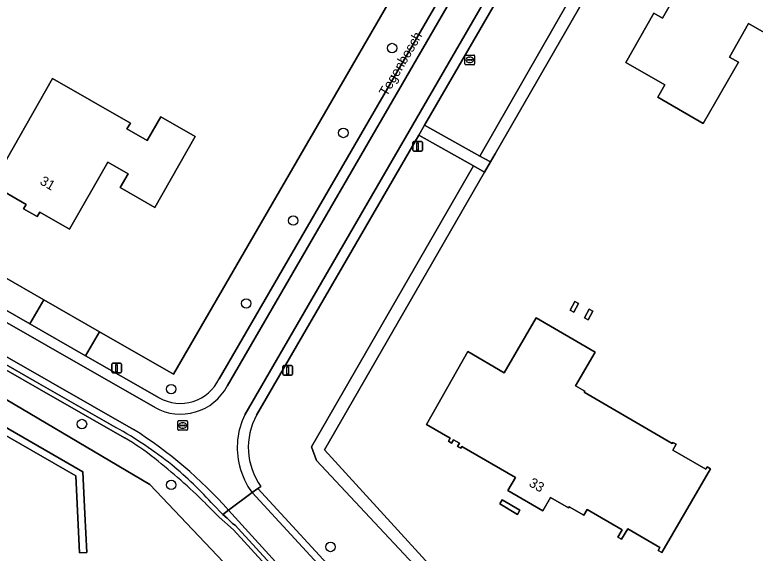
# Model space of a CAD drawing. Extents: x 156502 to 159075, y 384229 to 386100.
# Drawn here: x 157141.1 to 157217.5, y 385707.8 to 385763.4 of the extents above; entities that cross this region are included whole.
import ezdxf

# ---------------------------------------------------------------- set-up
doc = ezdxf.new("R2010")
doc.units = 0
for name, color, linetype in [('IMGEO_Berm_groen', 7, 'Continuous'), ('IMGEO_Berm_open', 7, 'Continuous'), ('IMGEO_Boom', 7, 'Continuous'), ('IMGEO_Erf', 7, 'Continuous'), ('IMGEO_Groenvoorziening', 7, 'Continuous'), ('IMGEO_Hek', 7, 'Continuous'), ('IMGEO_Kolk', 7, 'Continuous'), ('IMGEO_Lichtmast', 7, 'Continuous'), ('IMGEO_Muur', 7, 'Continuous'), ('IMGEO_Openbare_ruimte_label', 7, 'Continuous'), ('IMGEO_Pand', 7, 'Continuous'), ('IMGEO_Pand_nummerreeks', 7, 'Continuous'), ('IMGEO_Rijbaan_lokaal_gesloten', 7, 'Continuous'), ('IMGEO_Rijbaan_lokaal_halfverhard', 7, 'Continuous'), ('IMGEO_Rijbaan_lokaal_open', 7, 'Continuous'), ('IMGEO_Rioolput', 7, 'Continuous'), ('IMGEO_Voetpad_open', 7, 'Continuous')]:
    doc.layers.add(name, color=color, linetype=linetype)

msp = doc.modelspace()

# ---------------------------------------------------------------- linework, layer by layer
at = {"layer": 'IMGEO_Berm_groen'}
for points in [[(157205.798, 385801.093), (157204.517, 385807.457), (157201.732, 385802.693), (157157.489, 385726.3), (157149.855, 385730.69), (157148.433, 385728.196), (157156.009, 385723.887)], [(157162.191, 385725.838), (157205.798, 385801.093)]]:
    msp.add_lwpolyline(points, dxfattribs=at)
msp.add_lwpolyline([(157131.197, 385741.421), (157130.921, 385741.579), (157129.529, 385739.04), (157142.675, 385731.515), (157144.11, 385733.995)], close=True, dxfattribs=at)
msp.add_arc((157158.202, 385727.709), 4.406, 240.15556, 334.87517, dxfattribs=at)
at = {"layer": 'IMGEO_Berm_open'}
for points in [[(157122.692, 385736.917), (157122.629, 385736.809), (157134.443, 385730.048), (157136.699, 385728.757), (157143.67, 385724.768), (157152.438, 385719.741)], [(157151.556, 385720.809), (157143.135, 385725.639), (157131.139, 385732.504), (157122.862, 385737.211), (157122.692, 385736.917)], [(157160.802, 385712.985), (157162.212, 385711.565), (157163.676, 385710.253), (157166.599, 385707.057), (157167.262, 385706.33), (157167.069, 385705.548), (157165.011, 385703.658), (157164.518, 385703.205), (157164.798, 385702.861), (157164.874, 385702.768), (157167.579, 385705.215), (157167.865, 385706.331), (157164.162, 385710.397), (157163.893, 385710.681), (157163.596, 385710.912), (157163.015, 385711.443), (157162.571, 385711.837), (157162.514, 385711.888), (157161.64, 385712.801)]]:
    msp.add_lwpolyline(points, dxfattribs=at)
for centre, radius, start, end in [((157132.493, 385686.215), 39.499, 51.08239, 61.14287), ((157139.852, 385698.063), 25.067, 51.20506, 59.86057), ((157114.204, 385665.314), 66.663, 45.65222, 51.65962), ((157131.825, 385685.972), 40.109, 41.98216, 50.5579)]:
    msp.add_arc(centre, radius, start, end, dxfattribs=at)
at = {"layer": 'IMGEO_Boom'}
for centre in [(157180.048, 385759.963), (157175.016, 385751.204), (157169.847, 385742.161), (157164.994, 385733.609), (157157.253, 385724.77), (157148.052, 385721.166), (157157.263, 385714.892), (157173.691, 385708.485)]:
    msp.add_circle(centre, 0.489, dxfattribs=at)
at = {"layer": 'IMGEO_Erf'}
for points in [[(157131.197, 385741.421), (157144.11, 385733.995), (157149.855, 385730.69), (157157.489, 385726.3), (157201.732, 385802.693), (157194.383, 385806.952), (157190.645, 385800.522), (157181.547, 385805.765), (157180.811, 385804.505), (157181.113, 385804.328), (157176.827, 385796.988), (157169.771, 385801.108), (157174.018, 385808.44), (157178.814, 385805.661), (157179.553, 385806.928), (157179.259, 385807.099), (157183.031, 385813.57), (157159.85, 385827.054)], [(157300.611, 385725.628), (157250.886, 385753.432), (157232.436, 385728.117), (157222.966, 385734.271), (157242.958, 385769.961), (157246.925, 385776.791), (157216.71, 385794.202), (157213.481, 385788.661), (157210.483, 385783.472), (157204.894, 385773.824), (157204.086, 385772.373), (157190.66, 385749.032), (157190.191, 385748.219), (157189.585, 385747.166), (157173.064, 385718.503), (157188.558, 385701.554)], [(157130.083, 385674.016), (157162.143, 385703.286), (157165.17, 385704.25), (157155.054, 385714.92), (157136.059, 385726.15)], [(157134.817, 385723.916), (157148.149, 385716.222), (157148.362, 385711.898), (157148.558, 385707.925), (157147.812, 385707.892), (157147.432, 385715.812), (157133.773, 385723.654)]]:
    msp.add_lwpolyline(points, dxfattribs=at)
for points in [[(157216.825, 385762.498), (157214.836, 385759.028), (157215.782, 385758.513), (157212.125, 385752.188), (157207.442, 385754.89), (157208.164, 385756.155), (157204.143, 385758.489), (157207.06, 385763.557), (157207.934, 385763.062), (157209.905, 385766.51), (157209.04, 385767.011), (157210.228, 385769.058), (157211.364, 385771.036), (157210.092, 385771.773), (157212.805, 385776.435), (157227.391, 385767.994), (157224.692, 385763.333), (157223.414, 385764.038), (157221.09, 385760.054)], [(157145.011, 385756.807), (157153.044, 385752.202), (157152.682, 385751.64), (157154.769, 385750.435), (157156.174, 385752.869), (157159.745, 385750.827), (157155.568, 385743.525), (157151.995, 385745.568), (157152.803, 385746.981), (157150.715, 385748.193), (157146.759, 385741.271), (157143.69, 385743.027), (157143.418, 385742.572), (157142.025, 385743.36), (157142.291, 385743.83), (157136.743, 385747.004), (157136.902, 385747.281), (157138.903, 385746.106)], [(157198.789, 385732.728), (157198.416, 385732.933), (157198.908, 385733.827), (157199.28, 385733.622)], [(157200.256, 385731.922), (157199.883, 385732.127), (157200.374, 385733.02), (157200.747, 385732.816)], [(157212.394, 385716.506), (157212.545, 385716.767), (157212.9, 385716.561), (157207.88, 385707.905), (157207.492, 385708.134), (157207.663, 385708.425), (157204.36, 385710.352), (157203.719, 385709.283), (157203.343, 385709.503), (157203.783, 385710.251), (157200.181, 385712.353), (157199.832, 385711.755), (157198.312, 385712.63), (157198.242, 385712.509), (157196.392, 385713.576), (157195.606, 385712.212), (157191.984, 385714.299), (157192.772, 385715.665), (157187.236, 385718.855), (157187.126, 385718.663), (157186.796, 385718.851), (157186.992, 385719.194), (157186.385, 385719.542), (157186.189, 385719.199), (157185.859, 385719.388), (157186.052, 385719.726), (157183.587, 385721.136), (157187.86, 385728.639), (157191.62, 385726.449), (157194.896, 385732.112), (157200.992, 385728.586), (157198.967, 385725.104), (157199.927, 385724.546), (157199.867, 385724.443), (157208.946, 385719.168), (157209.006, 385719.272), (157209.343, 385719.076), (157208.997, 385718.479)], [(157192.972, 385711.834), (157191.144, 385712.919), (157191.405, 385713.359), (157193.232, 385712.273)]]:
    msp.add_lwpolyline(points, close=True, dxfattribs=at)
at = {"layer": 'IMGEO_Groenvoorziening'}
for points in [[(157202.954, 385773.026), (157197.423, 385776.216), (157183.392, 385751.998), (157189.099, 385748.819)], [(157204.086, 385772.373), (157203.479, 385772.723), (157202.954, 385773.026), (157189.099, 385748.819), (157189.61, 385748.533), (157190.191, 385748.219), (157190.66, 385749.032)], [(157173.064, 385718.503), (157189.585, 385747.166), (157188.458, 385747.796), (157171.716, 385718.804), (157172.234, 385717.388), (157187.763, 385700.816), (157188.558, 385701.554)]]:
    msp.add_lwpolyline(points, close=True, dxfattribs=at)
for points in [[(157188.458, 385747.796), (157182.79, 385750.96), (157166.062, 385722.087)], [(157166.5, 385714.736), (157166.189, 385714.515), (157177.304, 385702.459), (157182.888, 385696.288), (157187.763, 385700.816), (157172.234, 385717.388), (157171.716, 385718.804), (157188.458, 385747.796)], [(157152.438, 385719.741), (157143.67, 385724.768), (157136.699, 385728.757), (157135.417, 385726.51), (157136.059, 385726.15), (157155.054, 385714.92), (157165.17, 385704.25), (157165.011, 385703.658), (157167.069, 385705.548), (157167.262, 385706.33), (157166.599, 385707.057), (157163.676, 385710.253), (157162.212, 385711.565), (157160.802, 385712.985)]]:
    msp.add_lwpolyline(points, dxfattribs=at)
for centre, radius, start, end in [((157172.15, 385718.761), 6.937, 151.35104, 215.46869), ((157139.852, 385698.063), 25.067, 51.20506, 59.86057), ((157114.204, 385665.314), 66.663, 45.65222, 51.65962)]:
    msp.add_arc(centre, radius, start, end, dxfattribs=at)
at = {"layer": 'IMGEO_Hek'}
for points in [[(157149.855, 385730.69), (157157.489, 385726.3), (157201.732, 385802.693)], [(157131.197, 385741.421), (157144.11, 385733.995)], [(157144.11, 385733.995), (157149.855, 385730.69)]]:
    msp.add_lwpolyline(points, dxfattribs=at)
at = {"layer": 'IMGEO_Kolk'}
for p, q in [((157187.556, 385758.32), (157187.556, 385759.172)), ((157187.631, 385759.246), (157188.483, 385759.246)), ((157188.044, 385759.026), (157188.069, 385759.026)), ((157188.557, 385759.172), (157188.557, 385758.32)), ((157187.815, 385758.74), (157187.815, 385758.752)), ((157188.253, 385758.703), (157187.855, 385758.703)), ((157187.858, 385758.789), (157188.256, 385758.789)), ((157188.067, 385758.466), (157188.042, 385758.466)), ((157188.299, 385758.752), (157188.299, 385758.74)), ((157188.483, 385758.246), (157187.631, 385758.246))]:
    msp.add_line(p, q, dxfattribs=at)
for points in [[(157187.556, 385758.32), (157187.556, 385759.172)], [(157187.631, 385759.246), (157188.483, 385759.246)], [(157188.557, 385759.172), (157188.557, 385758.32)], [(157188.483, 385758.246), (157187.631, 385758.246)]]:
    msp.add_lwpolyline(points, dxfattribs=at)
for centre, radius, start, end in [((157187.633, 385759.17), 0.0765, 91.55205, 178.44795), ((157187.633, 385759.17), 0.0765, 91.55205, 178.44795), ((157188.481, 385759.17), 0.0765, 1.55205, 88.44795), ((157188.481, 385759.17), 0.0765, 1.55205, 88.44795), ((157187.633, 385758.322), 0.0765, 181.55205, 268.44795), ((157187.633, 385758.322), 0.0765, 181.55205, 268.44795), ((157187.855, 385758.749), 0.0403, 85.87752, 175.75265), ((157187.852, 385758.739), 0.0366, 178.93798, 274.71019), ((157188.256, 385758.746), 0.043, 264.86636, 352.45326), ((157188.26, 385758.751), 0.0386, 1.73085, 96.63898), ((157188.481, 385758.322), 0.0765, 271.55205, 358.44795), ((157188.481, 385758.322), 0.0765, 271.55205, 358.44795)]:
    msp.add_arc(centre, radius, start, end, dxfattribs=at)
for centre, major_axis, ratio, start_param, end_param in [((157188.043, 385758.746), (-0.387, 0.002), 0.722429, 4.712389, 7.853982), ((157188.068, 385758.746), (-0.39, 0.002), 0.717154, 1.570796, 4.712389)]:
    msp.add_ellipse(centre, major_axis=major_axis, ratio=ratio, start_param=start_param, end_param=end_param, dxfattribs=at)
at = {"layer": 'IMGEO_Lichtmast'}
for p, q in [((157182.18, 385749.418), (157182.18, 385750.218)), ((157182.18, 385750.218), (157182.18, 385749.418)), ((157182.28, 385750.318), (157183.07, 385750.318)), ((157183.07, 385750.318), (157182.28, 385750.318)), ((157183.17, 385750.218), (157183.17, 385749.418)), ((157183.17, 385749.418), (157183.17, 385750.218)), ((157183.07, 385749.318), (157182.28, 385749.318)), ((157182.28, 385749.318), (157183.07, 385749.318)), ((157151.129, 385726.54), (157151.129, 385727.34)), ((157151.129, 385727.34), (157151.129, 385726.54)), ((157151.229, 385727.44), (157152.019, 385727.44)), ((157152.019, 385727.44), (157151.229, 385727.44)), ((157152.119, 385727.34), (157152.119, 385726.54)), ((157152.119, 385726.54), (157152.119, 385727.34)), ((157168.777, 385726.301), (157168.777, 385727.101)), ((157168.777, 385727.101), (157168.777, 385726.301)), ((157168.877, 385727.201), (157169.667, 385727.201)), ((157169.667, 385727.201), (157168.877, 385727.201)), ((157169.767, 385727.101), (157169.767, 385726.301)), ((157169.767, 385726.301), (157169.767, 385727.101)), ((157152.019, 385726.44), (157151.229, 385726.44)), ((157151.229, 385726.44), (157152.019, 385726.44)), ((157169.667, 385726.201), (157168.877, 385726.201)), ((157168.877, 385726.201), (157169.667, 385726.201))]:
    msp.add_line(p, q, dxfattribs=at)
for points in [[(157182.6, 385750.193), (157182.75, 385750.193), (157182.75, 385749.443), (157182.6, 385749.443), (157182.6, 385750.193)], [(157151.549, 385727.315), (157151.699, 385727.315), (157151.699, 385726.565), (157151.549, 385726.565), (157151.549, 385727.315)], [(157169.197, 385727.076), (157169.347, 385727.076), (157169.347, 385726.326), (157169.197, 385726.326), (157169.197, 385727.076)]]:
    msp.add_lwpolyline(points, dxfattribs=at)
for centre, start, end in [((157182.28, 385750.218), 90, 180), ((157182.28, 385750.218), 90, 180), ((157183.07, 385750.218), 0, 90), ((157183.07, 385750.218), 360, 90), ((157182.28, 385749.418), 180, 270), ((157182.28, 385749.418), 180, 270), ((157183.07, 385749.418), 270, 0), ((157183.07, 385749.418), 270, 0), ((157151.229, 385727.34), 90, 180), ((157151.229, 385727.34), 90, 180), ((157152.019, 385727.34), 0, 90), ((157152.019, 385727.34), 360, 90), ((157168.877, 385727.101), 90, 180), ((157168.877, 385727.101), 90, 180), ((157169.667, 385727.101), 0, 90), ((157169.667, 385727.101), 360, 90), ((157151.229, 385726.54), 180, 270), ((157151.229, 385726.54), 180, 270), ((157152.019, 385726.54), 270, 0), ((157152.019, 385726.54), 270, 0), ((157168.877, 385726.301), 180, 270), ((157168.877, 385726.301), 180, 270), ((157169.667, 385726.301), 270, 0), ((157169.667, 385726.301), 270, 0)]:
    msp.add_arc(centre, 0.1, start, end, dxfattribs=at)
at = {"layer": 'IMGEO_Muur'}
msp.add_lwpolyline([(157148.362, 385711.898), (157148.149, 385716.222), (157134.817, 385723.916), (157136.059, 385726.15), (157135.417, 385726.51), (157134.821, 385725.475), (157133.773, 385723.654), (157147.432, 385715.812), (157147.812, 385707.892), (157148.558, 385707.925)], close=True, dxfattribs=at)
at = {"layer": 'IMGEO_Pand'}
for points in [[(157227.391, 385767.994), (157212.805, 385776.435), (157210.092, 385771.773), (157211.364, 385771.036), (157210.228, 385769.058), (157209.04, 385767.011), (157209.905, 385766.51), (157207.934, 385763.062), (157207.06, 385763.557), (157204.143, 385758.489), (157208.164, 385756.155), (157207.442, 385754.89), (157212.125, 385752.188), (157215.782, 385758.513), (157214.836, 385759.028), (157216.825, 385762.498), (157221.09, 385760.054), (157223.414, 385764.038), (157224.692, 385763.333)], [(157146.759, 385741.271), (157150.715, 385748.193), (157152.803, 385746.981), (157151.995, 385745.568), (157155.568, 385743.525), (157159.745, 385750.827), (157156.174, 385752.869), (157154.769, 385750.435), (157152.682, 385751.64), (157153.044, 385752.202), (157145.011, 385756.807), (157138.903, 385746.106), (157136.902, 385747.281), (157136.743, 385747.004), (157142.291, 385743.83), (157142.025, 385743.36), (157143.418, 385742.572), (157143.69, 385743.027)], [(157199.28, 385733.622), (157198.908, 385733.827), (157198.416, 385732.933), (157198.789, 385732.728)], [(157200.747, 385732.816), (157200.374, 385733.02), (157199.883, 385732.127), (157200.256, 385731.922)], [(157199.867, 385724.443), (157199.927, 385724.546), (157198.967, 385725.104), (157200.992, 385728.586), (157194.896, 385732.112), (157191.62, 385726.449), (157187.86, 385728.639), (157183.587, 385721.136), (157186.052, 385719.726), (157185.859, 385719.388), (157186.189, 385719.199), (157186.385, 385719.542), (157186.992, 385719.194), (157186.796, 385718.851), (157187.126, 385718.663), (157187.236, 385718.855), (157192.772, 385715.665), (157191.984, 385714.299), (157195.606, 385712.212), (157196.392, 385713.576), (157198.242, 385712.509), (157198.312, 385712.63), (157199.832, 385711.755), (157200.181, 385712.353), (157203.783, 385710.251), (157203.343, 385709.503), (157203.719, 385709.283), (157204.36, 385710.352), (157207.663, 385708.425), (157207.492, 385708.134), (157207.88, 385707.905), (157212.9, 385716.561), (157212.545, 385716.767), (157212.394, 385716.506), (157208.997, 385718.479), (157209.343, 385719.076), (157209.006, 385719.272), (157208.946, 385719.168)], [(157191.144, 385712.919), (157192.972, 385711.834), (157193.232, 385712.273), (157191.405, 385713.359)]]:
    msp.add_lwpolyline(points, close=True, dxfattribs=at)
at = {"layer": 'IMGEO_Rijbaan_lokaal_gesloten'}
for points in [[(157164.84, 385722.131), (157211.808, 385803.246), (157209.184, 385804.754), (157163.025, 385725.068)], [(157155.604, 385722.866), (157042.417, 385787.656)], [(157047.474, 385781.289), (157153.385, 385720.619)], [(157163.176, 385712.295), (157165.598, 385714.094)]]:
    msp.add_lwpolyline(points, dxfattribs=at)
for centre, radius, start, end in [((157158.231, 385727.619), 5.431, 241.07519, 331.97874), ((157171.922, 385718.745), 7.85, 154.44814, 194.01694), ((157126.977, 385679.637), 48.753, 42.05634, 57.20338), ((157171.939, 385718.751), 7.867, 194.03127, 216.29872)]:
    msp.add_arc(centre, radius, start, end, dxfattribs=at)
at = {"layer": 'IMGEO_Rijbaan_lokaal_halfverhard'}
for points in [[(157163.025, 385725.068), (157209.184, 385804.754), (157204.517, 385807.457), (157205.798, 385801.093), (157162.191, 385725.838)], [(157042.417, 385787.656), (157155.604, 385722.866)], [(157156.009, 385723.887), (157148.433, 385728.196), (157142.675, 385731.515), (157129.529, 385739.04), (157126.176, 385740.973), (157123.969, 385742.234), (157121.61, 385743.581), (157120.125, 385744.429), (157117.587, 385745.884), (157112.582, 385748.755), (157110.239, 385750.099), (157105.201, 385752.99), (157098.368, 385756.889), (157083.861, 385765.187), (157082.83, 385765.787), (157073.474, 385771.108), (157068.127, 385774.18), (157061.801, 385777.83), (157055.407, 385781.512), (157048.506, 385785.444), (157044.158, 385787.921)], [(157047.474, 385781.289), (157047.846, 385779.743), (157048.686, 385779.263), (157061.322, 385772.036), (157075.399, 385763.984), (157081.499, 385760.496), (157110.277, 385744.036), (157115.815, 385740.863), (157122.692, 385736.917), (157122.862, 385737.211), (157131.139, 385732.504), (157143.135, 385725.639), (157151.556, 385720.809)], [(157153.385, 385720.619), (157047.474, 385781.289)], [(157161.64, 385712.801), (157162.514, 385711.888), (157162.571, 385711.837), (157163.176, 385712.295)], [(157163.176, 385712.295), (157162.571, 385711.837), (157163.015, 385711.443), (157163.596, 385710.912), (157163.893, 385710.681), (157164.162, 385710.397), (157167.865, 385706.331), (157168.522, 385705.66), (157168.384, 385705.534), (157168.762, 385705.12), (157178.323, 385694.641), (157187.069, 385685.078), (157189.05, 385682.889)], [(157189.594, 385683.36), (157187.603, 385685.561), (157178.854, 385695.127), (157169.409, 385705.442), (157163.176, 385712.295)]]:
    msp.add_lwpolyline(points, dxfattribs=at)
msp.add_lwpolyline([(157166.189, 385714.515), (157165.598, 385714.094), (157176.77, 385701.976), (157182.361, 385695.797), (157182.888, 385696.288), (157177.304, 385702.459)], close=True, dxfattribs=at)
for centre, radius, start, end in [((157158.202, 385727.709), 4.406, 240.15556, 334.87517), ((157158.231, 385727.619), 5.431, 241.07519, 331.97874), ((157132.493, 385686.215), 39.499, 51.08239, 61.14287), ((157126.977, 385679.637), 48.753, 42.05634, 57.20338), ((157131.825, 385685.972), 40.109, 41.98216, 50.5579)]:
    msp.add_arc(centre, radius, start, end, dxfattribs=at)
at = {"layer": 'IMGEO_Rijbaan_lokaal_open'}
for points in [[(157203.866, 385787.336), (157206.888, 385792.553), (157210.12, 385798.131), (157215.153, 385806.818), (157214.196, 385807.371), (157211.808, 385803.246), (157164.84, 385722.131)], [(157166.062, 385722.087), (157182.79, 385750.96), (157183.392, 385751.998), (157197.423, 385776.216), (157198.256, 385777.654), (157203.866, 385787.336)], [(157165.598, 385714.094), (157166.189, 385714.515), (157166.5, 385714.736)], [(157193.263, 385683.914), (157187.308, 385690.372), (157185.26, 385692.593), (157182.361, 385695.797), (157176.77, 385701.976), (157165.598, 385714.094), (157163.176, 385712.295), (157169.409, 385705.442), (157178.854, 385695.127), (157187.603, 385685.561), (157189.594, 385683.36)]]:
    msp.add_lwpolyline(points, dxfattribs=at)
msp.add_lwpolyline([(157142.675, 385731.515), (157148.433, 385728.196), (157149.855, 385730.69), (157144.11, 385733.995)], close=True, dxfattribs=at)
for centre, radius, start, end in [((157171.922, 385718.745), 7.85, 154.44814, 194.01694), ((157172.15, 385718.761), 6.937, 151.35104, 215.46869), ((157171.939, 385718.751), 7.867, 194.03127, 216.29872)]:
    msp.add_arc(centre, radius, start, end, dxfattribs=at)
at = {"layer": 'IMGEO_Rioolput'}
for p, q in [((157157.94, 385720.593), (157157.94, 385721.445)), ((157158.015, 385721.519), (157158.867, 385721.519)), ((157158.199, 385721.013), (157158.199, 385721.025)), ((157158.637, 385720.976), (157158.239, 385720.976)), ((157158.242, 385721.062), (157158.64, 385721.062)), ((157158.428, 385721.299), (157158.453, 385721.299)), ((157158.683, 385721.025), (157158.683, 385721.013)), ((157158.941, 385721.445), (157158.941, 385720.593)), ((157158.867, 385720.519), (157158.015, 385720.519)), ((157158.451, 385720.739), (157158.426, 385720.739))]:
    msp.add_line(p, q, dxfattribs=at)
for points in [[(157157.94, 385720.593), (157157.94, 385721.445)], [(157158.015, 385721.519), (157158.867, 385721.519)], [(157158.941, 385721.445), (157158.941, 385720.593)], [(157158.867, 385720.519), (157158.015, 385720.519)]]:
    msp.add_lwpolyline(points, dxfattribs=at)
for centre, radius, start, end in [((157158.017, 385721.443), 0.0765, 91.55205, 178.44795), ((157158.017, 385721.443), 0.0765, 91.55205, 178.44795), ((157158.239, 385721.022), 0.0403, 85.87752, 175.75265), ((157158.236, 385721.012), 0.0366, 178.93798, 274.71019), ((157158.64, 385721.019), 0.043, 264.86636, 352.45326), ((157158.644, 385721.024), 0.0386, 1.73085, 96.63898), ((157158.865, 385721.443), 0.0765, 1.55205, 88.44795), ((157158.865, 385721.443), 0.0765, 1.55205, 88.44795), ((157158.017, 385720.595), 0.0765, 181.55205, 268.44795), ((157158.017, 385720.595), 0.0765, 181.55205, 268.44795), ((157158.865, 385720.595), 0.0765, 271.55205, 358.44795), ((157158.865, 385720.595), 0.0765, 271.55205, 358.44795)]:
    msp.add_arc(centre, radius, start, end, dxfattribs=at)
for centre, major_axis, ratio, start_param, end_param in [((157158.427, 385721.019), (-0.387, 0.002), 0.722429, 4.712389, 7.853982), ((157158.452, 385721.019), (-0.39, 0.002), 0.717154, 1.570796, 4.712389)]:
    msp.add_ellipse(centre, major_axis=major_axis, ratio=ratio, start_param=start_param, end_param=end_param, dxfattribs=at)
at = {"layer": 'IMGEO_Voetpad_open'}
msp.add_lwpolyline([(157183.392, 385751.998), (157182.79, 385750.96), (157188.458, 385747.796), (157189.585, 385747.166), (157190.191, 385748.219), (157189.61, 385748.533), (157189.099, 385748.819)], close=True, dxfattribs=at)

# ---------------------------------------------------------------- texts
at = {"layer": 'IMGEO_Openbare_ruimte_label'}
msp.add_text('Tegenbosch', height=1, rotation=59.79307, dxfattribs=at).set_placement((157179.489, 385754.913))
at = {"layer": 'IMGEO_Pand_nummerreeks'}
for s, rotation, p in [('31', 330.15257, (157143.626, 385745.969)), ('33', 330.0515, (157194.083, 385714.821))]:
    msp.add_text(s, height=1, rotation=rotation, dxfattribs=at).set_placement(p)

doc.saveas('drawing.dxf')
